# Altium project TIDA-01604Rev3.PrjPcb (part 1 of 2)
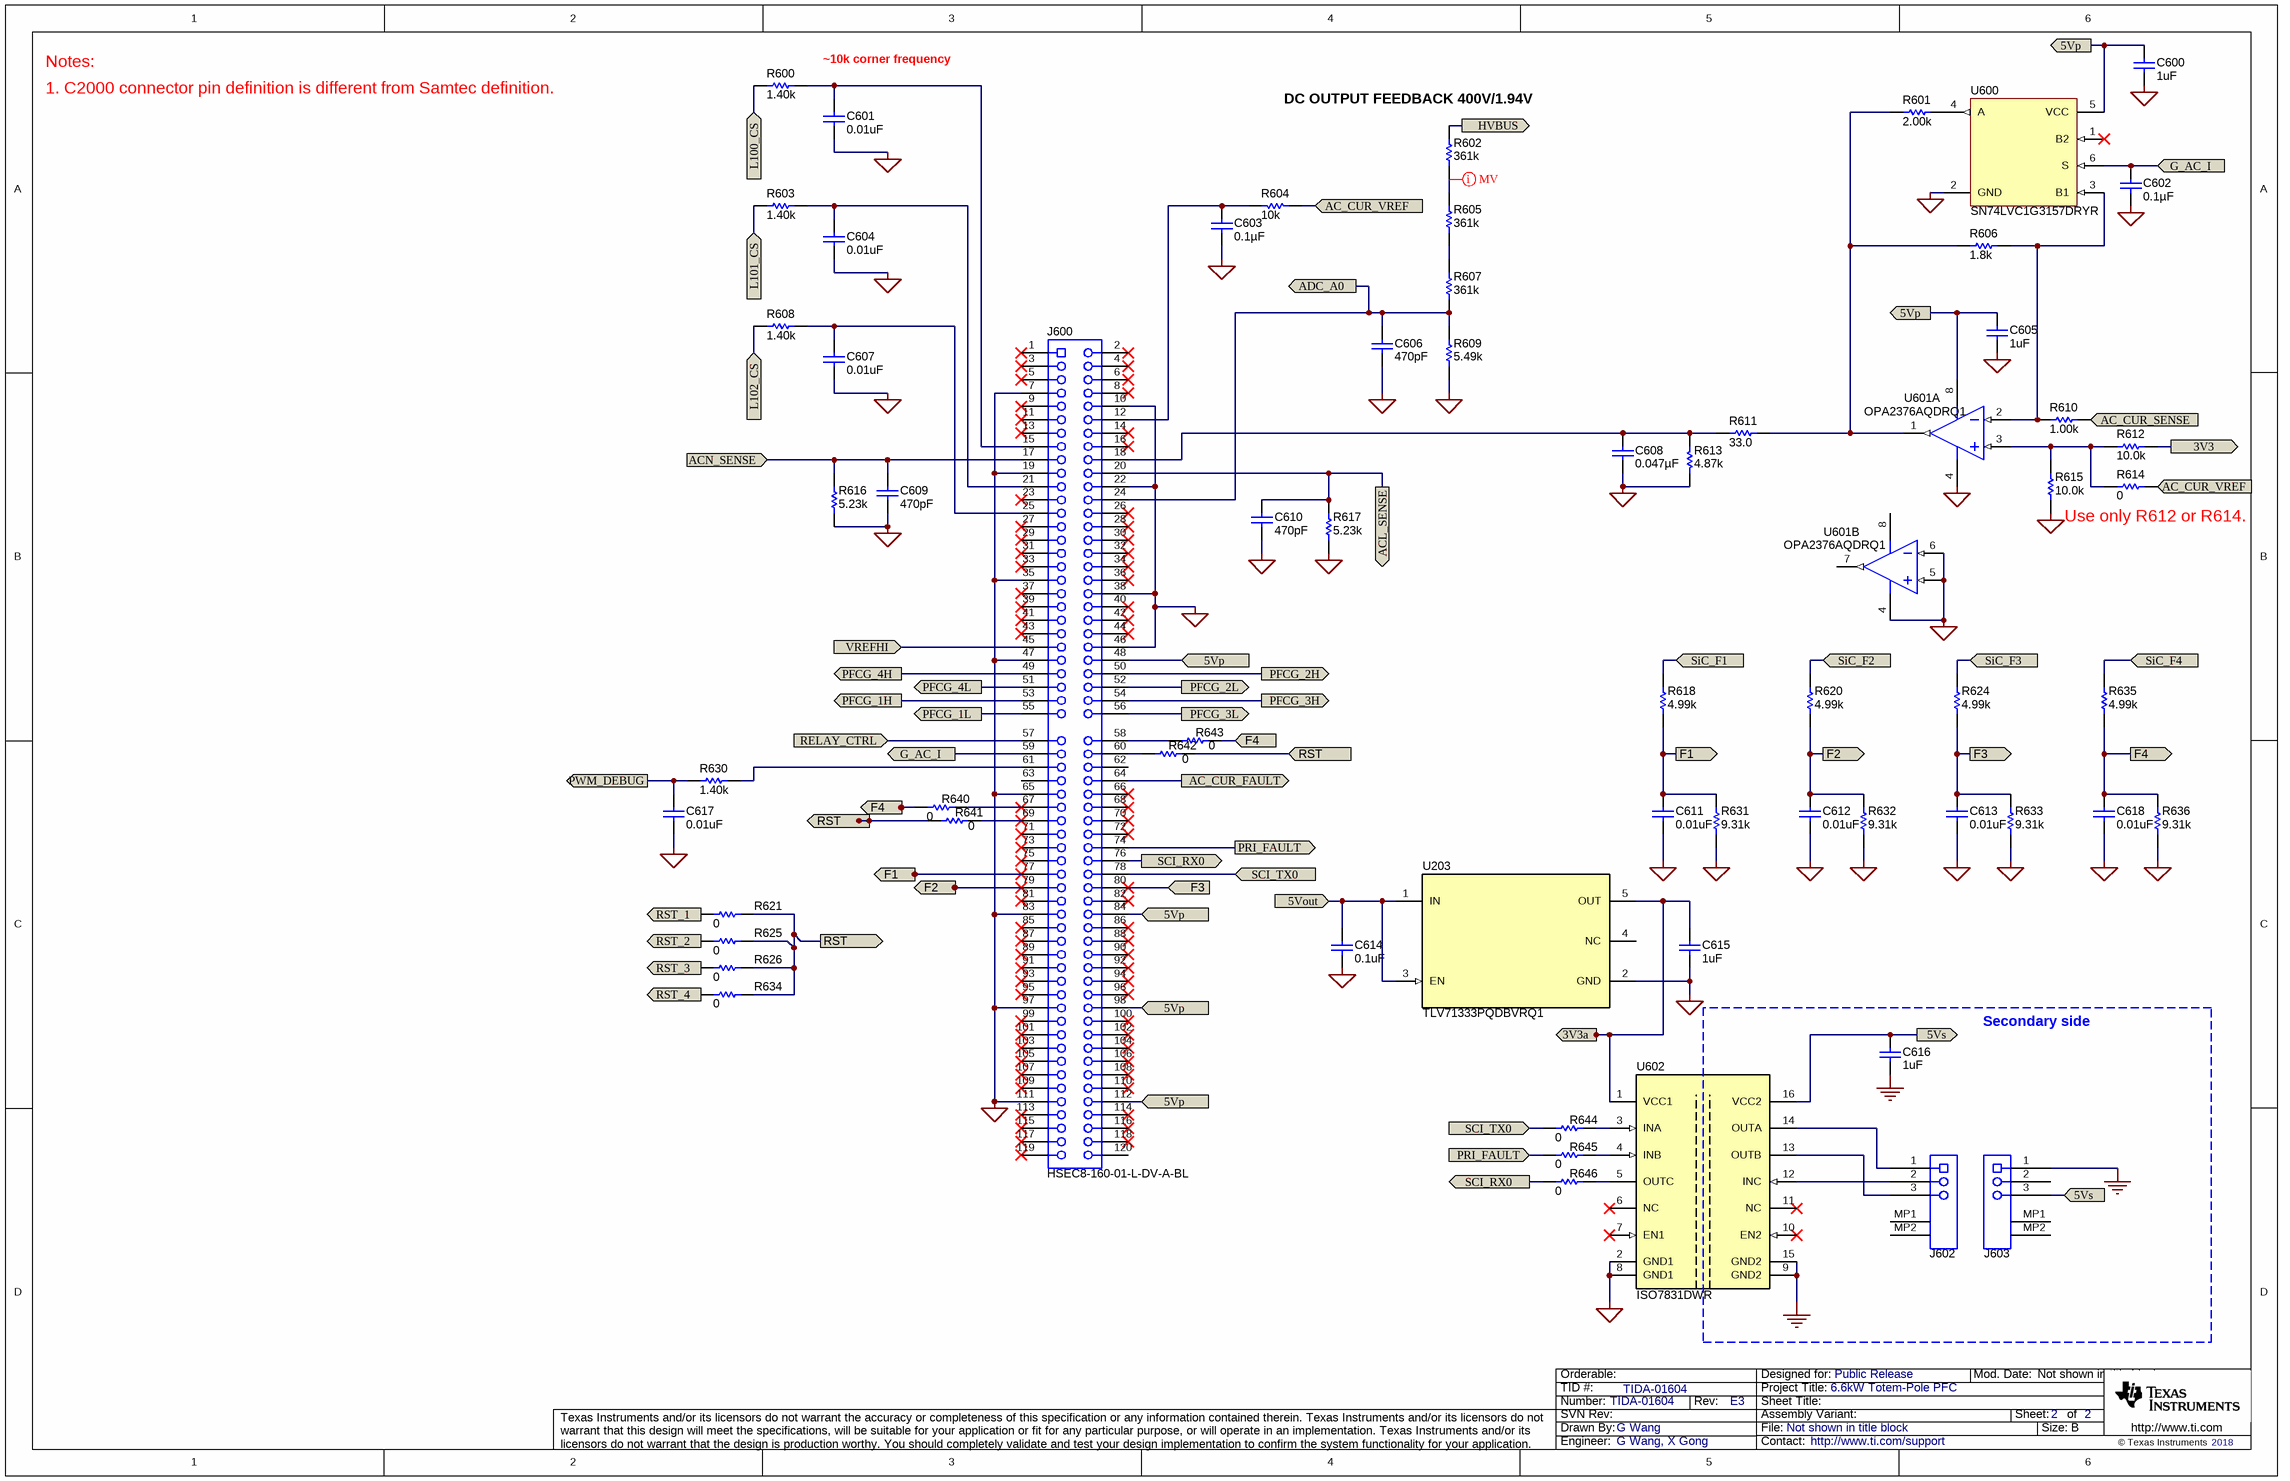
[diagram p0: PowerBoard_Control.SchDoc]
CopyrightYear: 2018; PCB_Layout: G Wang, X Gong; PCB_Rev: E3; PRJ_Customer: Public Release; PRJ_Engineer: G Wang, X Gong; PRJ_Number: TIDA-01604; PRJ_Title: 6.6kW Totem-Pole PFC; SCH_Rev: E3; TechSupport: http://www.ti.com/support; TID: TIDA-01604
3 sheets, 243 parts. Net scope: flat (ports and power ports of the same name join across sheets).
Board file: PowerBoard_PCB.PcbDoc
Sheets:
  PowerBoard_Control.SchDoc
  EVM_Hardware1.SchDoc
  PowerBoard.SchDoc

## Sheet PowerBoard_Control.SchDoc
size 431 x 279 mm; Date: Not shown in title block; ApprovedBy: Not shown in title block; CheckedBy: Not shown in title block; Author: Not shown in title block; CompanyName: Not shown in title block; DrawnBy: G Wang; Engineer: Not shown in title block; Organization: Not shown in title block; Address1: Not shown in title block; Address2: Not shown in title block; Address3: Not shown in title block; Address4: Not shown in title block; DocumentNumber: 2; Revision: Use project parameter SCH_Rev; SheetNumber: 2; SheetTotal: 2; PageSetup: Record=PageOptions¦CenterHorizontal=True¦CenterVertical=True¦PrintScale=1.00¦XCorrection=1.00¦YCorrection=1.00¦PrintKind=0¦BorderSize=5000000¦LeftOffset=0¦BottomOffset=0¦Orientation=2¦PaperLength=1000¦PaperWidth=1000¦Scale=100¦PaperSource=15¦PrintQuality=600¦MediaType=1¦DitherType=10¦PaperKind=Letter¦PrintScaleMode=1

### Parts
C600  ValueDisplayed: 1uF  [0603]  (hidden comment: C1608X7R1E105K080AB)
C601  ValueDisplayed: 0.01uF  [0402]  (hidden comment: GRM155R70J103KA01D)
C602  ValueDisplayed: 0.1µF  [0402]  (hidden comment: GCM155R71C104KA55D)
C603  ValueDisplayed: 0.1µF  [0402]  (hidden comment: GRM155R60J104KA01D)
C604  ValueDisplayed: 0.01uF  [0402]  (hidden comment: GRM155R70J103KA01D)
C605  ValueDisplayed: 1uF  [0603]  (hidden comment: C1608X7R1E105K080AB)
C606  ValueDisplayed: 470pF  [0402]  (hidden comment: GRM1555C1H471JA01D)
C607  ValueDisplayed: 0.01uF  [0402]  (hidden comment: GRM155R70J103KA01D)
C608  ValueDisplayed: 0.047µF  [0402]  (hidden comment: GRM155R60J472KA01D)
C609  ValueDisplayed: 470pF  [0402]  (hidden comment: GRM1555C1H471JA01D)
C610  ValueDisplayed: 470pF  [0402]  (hidden comment: GRM1555C1H471JA01D)
C611  ValueDisplayed: 0.01uF  [0402]  (hidden comment: GRM155R70J103KA01D)
C612  ValueDisplayed: 0.01uF  [0402]  (hidden comment: GRM155R70J103KA01D)
C613  ValueDisplayed: 0.01uF  [0402]  (hidden comment: GRM155R70J103KA01D)
C614  ValueDisplayed: 0.1uF  [0402]  (hidden comment: GRM155R70J104KA01D)
C615  ValueDisplayed: 1uF  [0603]  (hidden comment: C1608X7R1E105K080AB)
C616  ValueDisplayed: 1uF  [0603]  (hidden comment: C1608X7R1E105K080AB)
C617  ValueDisplayed: 0.01uF  [0402]  (hidden comment: GRM155R70J103KA01D)
C618  ValueDisplayed: 0.01uF  [0402]  (hidden comment: GRM155R70J103KA01D)
J600  HSEC8-160-01-L-DV-A-BL  [controlCARD-120HSEC]
J602  DF59-3S-2V(51)  [Hirose_DF59-3S-2V_51]  (value not drawn)
J603  DF59-3S-2V(51)  [Hirose_DF59-3S-2V_51]  (value not drawn)
R600  value 1.40k  [0402]  (hidden comment: CRCW04021K40FKED)
R601  ValueDisplayed: 2.00k  [0402]  (hidden comment: CRCW04022K00FKED)
R602  ValueDisplayed: 361k  [0805_HV]  (hidden comment: RT0805BRD07361KL)
R603  value 1.40k  [0402]  (hidden comment: CRCW04021K40FKED)
R604  value 10k  [0402]  (hidden comment: CRCW040210K0JNED)
R605  ValueDisplayed: 361k  [0805_HV]  (hidden comment: RT0805BRD07361KL)
R606  ValueDisplayed: 1.8k  [0402]  (hidden comment: CRCW04023K92FKED)
R607  ValueDisplayed: 361k  [0805_HV]  (hidden comment: RT0805BRD07361KL)
R608  value 1.40k  [0402]  (hidden comment: CRCW04021K40FKED)
R609  ValueDisplayed: 5.49k  [0805_HV]  (hidden comment: CRCW08055K49FKEA)
R610  ValueDisplayed: 1.00k  [0402]  (hidden comment: CRCW04021K00FKED)
R611  ValueDisplayed: 33.0  [0402]  (hidden comment: RC0402FR-0733RL)
R612  ValueDisplayed: 10.0k  [0402]  (hidden comment: CRCW040210K0FKED)  (no BOM)
R613  ValueDisplayed: 4.87k  [0402]  (hidden comment: ERA-2AEB4871X)
R614  ValueDisplayed: 0  [0402]  (hidden comment: CRCW04020000Z0ED)
R615  ValueDisplayed: 10.0k  [0402]  (hidden comment: CRCW040210K0FKED)
R616  ValueDisplayed: 5.23k  [0402]  (hidden comment: CRCW04025K23FKED)
R617  ValueDisplayed: 5.23k  [0402]  (hidden comment: CRCW04025K23FKED)
R618  ValueDisplayed: 4.99k  [0402]  (hidden comment: CRCW04024K99FKED)
R620  ValueDisplayed: 4.99k  [0402]  (hidden comment: CRCW04024K99FKED)
R621  ValueDisplayed: 0  [0402]  (hidden comment: CRCW04020000Z0ED)
R624  ValueDisplayed: 4.99k  [0402]  (hidden comment: CRCW04024K99FKED)
R625  ValueDisplayed: 0  [0402]  (hidden comment: CRCW04020000Z0ED)
R626  ValueDisplayed: 0  [0402]  (hidden comment: CRCW04020000Z0ED)
R630  value 1.40k  [0402]  (hidden comment: CRCW04021K40FKED)
R631  ValueDisplayed: 9.31k  [0402]  (hidden comment: CRCW04029K31FKED)
R632  ValueDisplayed: 9.31k  [0402]  (hidden comment: CRCW04029K31FKED)
R633  ValueDisplayed: 9.31k  [0402]  (hidden comment: CRCW04029K31FKED)
R634  ValueDisplayed: 0  [0402]  (hidden comment: CRCW04020000Z0ED)
R635  ValueDisplayed: 4.99k  [0402]  (hidden comment: CRCW04024K99FKED)
R636  ValueDisplayed: 9.31k  [0402]  (hidden comment: CRCW04029K31FKED)
R640  ValueDisplayed: 0  [0402]  (hidden comment: CRCW04020000Z0ED)
R641  ValueDisplayed: 0  [0402]  (hidden comment: CRCW04020000Z0ED)
R642  ValueDisplayed: 0  [0402]  (hidden comment: CRCW04020000Z0ED)
R643  ValueDisplayed: 0  [0402]  (hidden comment: CRCW04020000Z0ED)
R644  ValueDisplayed: 0  [0402]  (hidden comment: CRCW04020000Z0ED)
R645  ValueDisplayed: 0  [0402]  (hidden comment: CRCW04020000Z0ED)
R646  ValueDisplayed: 0  [0402]  (hidden comment: CRCW04020000Z0ED)
U203  TLV71333PQDBVRQ1  [DBV0005A_N]
U600  SN74LVC1G3157DRYR  [DRY0006A]
U601  OPA2376AQDRQ1  [D0008A_N]  (parts A,B of 2)
U602  ISO7831DWR  [DW0016B_N]

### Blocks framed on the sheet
Secondary side: C616 J602 J603 U602

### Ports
3V3 (out), 3V3a, 5Vout, 5Vp, 5Vs, AC_CUR_FAULT, AC_CUR_SENSE, AC_CUR_VREF, ACL_SENSE, ACN_SENSE, ADC_A0 (out), F1 (in), F1 (out), F2 (in), F2 (out), F3 (in), F3 (out), F4, F4 (out), G_AC_I (in), G_AC_I (out), HVBUS, L100_CS (in), L101_CS (in), L102_CS (in), PFCG_1H (out), PFCG_1L (out), PFCG_2H (out), PFCG_2L (out), PFCG_3H (out), PFCG_3L (out), PFCG_4H (out), PFCG_4L (out), PRI_FAULT (in), PRI_FAULT (out), PWM_DEBUG (out), RELAY_CTRL, RST, RST (out), RST_1 (out), RST_2 (out), RST_3 (out), RST_4 (out), SCI_RX0 (out), SCI_TX0, SCI_TX0 (in), SiC_F1 (in), SiC_F2 (in), SiC_F3 (in), SiC_F4 (in), VREFHI (in)

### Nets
PGND: C600.1 C601.2 C602.2 C603.1 C604.2 C605.1 C606.2 C607.2 C608.2 C609.2 C610.2 C611.2 C612.2 C613.2 C614.2 C615.1 C617.2 C618.2 J600.7 J600.10 J600.19 J600.22 J600.35 J600.38 J600.46 J600.47 J600.65 J600.83 J600.97 J600.111 R609.1 R613.1 R615.1 R616.1 R617.1 R631.1 R632.1 R633.1 R636.1 U203.2(GND) U600.2(GND) U601.4(V-) U601.5(IN_B+) U601.6(IN_B-) U602.2(GND1) U602.8(GND1)
SGND2: C616.1 J603.1 U602.9(GND2) U602.15(GND2)
3V3: R612.2 ; port 3V3
3V3a: C615.2 U203.5(OUT) U602.1(VCC1) ; port 3V3a
5Vout: C614.1 U203.1(IN) U203.3(EN) ; port 5Vout
5Vp: C600.2 C605.2 J600.48 J600.84 J600.98 J600.112 U600.5(VCC) U601.8(V+) ; port 5Vp
5Vs: C616.2 J603.3 U602.16(VCC2) ; port 5Vs
AC_CUR_FAULT: J600.64 ; port AC_CUR_FAULT
AC_CUR_SENSE: R610.1 ; port AC_CUR_SENSE
AC_CUR_VREF: R604.2 R614.2 ; port AC_CUR_VREF
ACL_SENSE: C610.1 J600.20 R617.2 ; port ACL_SENSE
ACN_SENSE: C609.1 J600.17 R616.2 ; port ACN_SENSE
ADC_A0: C606.1 J600.24 R607.2 R609.2 ; port ADC_A0
F1: C611.1 J600.77 R618.1 R631.2 ; port F1
F2: C612.1 J600.79 R620.1 R632.2 ; port F2
F3: C613.1 J600.80 R624.1 R633.2 ; port F3
F4: C618.1 R635.1 R636.2 R640.1 R643.2 ; port F4
G_AC_I: C602.1 J600.59 U600.6(S) ; port G_AC_I
HVBUS: R602.2 ; port HVBUS
L100_CS: R600.1 ; port L100_CS
L101_CS: R603.1 ; port L101_CS
L102_CS: R608.1 ; port L102_CS
PFCG_1H: J600.53 ; port PFCG_1H
PFCG_1L: J600.55 ; port PFCG_1L
PFCG_2H: J600.50 ; port PFCG_2H
PFCG_2L: J600.52 ; port PFCG_2L
PFCG_3H: J600.54 ; port PFCG_3H
PFCG_3L: J600.56 ; port PFCG_3L
PFCG_4H: J600.49 ; port PFCG_4H
PFCG_4L: J600.51 ; port PFCG_4L
PRI_FAULT: J600.74 R645.1 ; port PRI_FAULT
PWM_DEBUG: C617.1 R630.1 ; port PWM_DEBUG
RELAY_CTRL: J600.57 ; port RELAY_CTRL
RST: R621.2 R625.2 R626.2 R634.2 R641.1 R642.2 ; port RST
RST_1: R621.1 ; port RST_1
RST_2: R625.1 ; port RST_2
RST_3: R626.1 ; port RST_3
RST_4: R634.1 ; port RST_4
SCI_RX0: J600.76 R646.1 ; port SCI_RX0
SCI_TX0: J600.78 R644.1 ; port SCI_TX0
SiC_F1: R618.2 ; port SiC_F1
SiC_F2: R620.2 ; port SiC_F2
SiC_F3: R624.2 ; port SiC_F3
SiC_F4: R635.2 ; port SiC_F4
VREFHI: J600.45 ; port VREFHI
NetC601_1: C601.1 J600.15 R600.2
NetC603_2: C603.2 J600.12 R604.1
NetC604_1: C604.1 J600.21 R603.2
NetC607_1: C607.1 J600.25 R608.2
NetC608_1: C608.1 J600.18 R611.1 R613.2
NetJ600_58: J600.58 R643.1
NetJ600_60: J600.60 R642.1
NetJ600_61: J600.61 R630.2
NetJ600_67: J600.67 R640.2
NetJ600_69: J600.69 R641.2
NetJ602_1: J602.1 U602.14(OUTA)
NetJ602_2: J602.2 U602.12(INC)
NetJ602_3: J602.3 U602.13(OUTB)
NetR601_1: R601.1 R606.1 R611.2 U601.1(OUT_A)
NetR601_2: R601.2 U600.4(A)
NetR602_1: R602.1 R605.1
NetR605_2: R605.2 R607.1
NetR606_2: R606.2 R610.2 U600.3(B1) U601.2(IN_A-)
NetR612_1: R612.1 R614.1 R615.2 U601.3(IN_A+)
NetR644_2: R644.2 U602.3(INA)
NetR645_2: R645.2 U602.4(INB)
NetR646_2: R646.2 U602.5(OUTC)

Not connected (* = marked no-connect by the designer): J600 1* 2* 3* 4* 5* 6* 8* 9* 11* 13* 14* 16* 23* 26* 27* 28* 29* 30* 31* 32* 33* 34* 36* 37* 39* 40* 41* 42* 43* 44* 62 63 66* 68* 70* 71* 72* 73* 75* 81* 82* 85* 86* 87* 88* 89* 90* 91* 92* 93* 94* 95* 96* 99* 100* 101* 102* 103* 104* 105* 106* 107* 108* 109* 110* 113* 114* 115* 116* 117* 118* 119* 120; J602 MP1 MP2; J603 2 MP1 MP2; U203 4(NC); U600 1(B2)*; U601 7(OUT_B); U602 6(NC)* 7(EN1)* 10(EN2)* 11(NC)*

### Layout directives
net class MV: NetR602_1

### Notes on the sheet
- Notes:
- 1. C2000 connector pin definition is different from Samtec definition.
- 0k corner frequency
- (near R602) DC OUTPUT FEEDBACK 400V/1.94V
- Use only R612 or R614.

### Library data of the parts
C600 C605 C615 C616 = C1608X7R1E105K080AB: CAP, CERM, 1uF, 25V, +/-10%, X7R, 0603; Manufacturer: TDK; Polarized: N; CompType: Capacitor; U/M: EA; Cap_F: 0.000001; Tolerance_%: 10; Value1: Unknown; VDC_V: 25; TaMin_C: -55; TaMax_C: 125
C601 C604 C607 C611-C613 C617 C618 = GRM155R70J103KA01D: CAP, CERM, 0.01uF, 6.3V, +/-10%, X7R, 0402; Manufacturer: MuRata; Polarized: N; CompType: Capacitor; U/M: EA; Cap_F: 0.00000001; Tolerance_%: 10; Value1: Unknown; VDC_V: 6.3; TaMin_C: -55; TaMax_C: 125
C602 = GCM155R71C104KA55D: CAP, CERM, 0.1 µF, 16 V, +/- 10%, X7R, 0402; Manufacturer: MuRata; Polarized: N; CompType: Capacitor; Value: 0.1uF; U/M: EA; Cap_F: 0.0000001; Tolerance_%: 10; Value1: Unknown; VDC_V: 16; Value2: 16V; TaMin_C: -55; TaMax_C: 125; SizeArea_mm2: 0.5; SizeAreaWB_mm2: 3; SizeX_mm: 1; SizeZ_mm: 0.6; AEC Category: Q200
C603 = GRM155R60J104KA01D: CAP, CERM, 0.1uF, 6.3V, +/-10%, X5R, 0402; Manufacturer: MuRata; Polarized: N; CompType: Capacitor; U/M: EA; Cap_F: 0.0000001; Tolerance_%: 10; Value1: Unknown; VDC_V: 6.3; TaMin_C: -55; TaMax_C: 85
C606 C609 C610 = GRM1555C1H471JA01D: CAP, CERM, 470 pF, 50 V,+/- 5%, C0G/NP0, 0402; Manufacturer: MuRata; Polarized: N; CompType: Capacitor; Value: 470pF; U/M: EA; Cap_F: 0.00000000047; Tolerance_%: 5; VDC_V: 50; Value2: 50V; TaMin_C: -55; TaMax_C: 125; SizeArea_mm2: 0.5; SizeAreaWB_mm2: 3; SizeX_mm: 1; SizeZ_mm: 0.6; AEC Category: Q200; Green_Lifecycle: Active; Green_REACh: Passed
C608 = C1005X5R1A473K050BA: CAP, CERM, 0.047 µF, 10 V, +/- 10%, X5R, 0402; Manufacturer: TDK; Polarized: N; CompType: Capacitor; Value: 0.047uF; U/M: EA; Cap_F: 0.000000047; Tolerance_%: 10; Value1: Unknown; Value2: 10V; TaMin_C: -55; TaMax_C: 85; SizeArea_mm2: 0.5; SizeAreaWB_mm2: 3; SizeX_mm: 1; SizeZ_mm: 0.6; AEC Category: Q200
C614 = GRM155R70J104KA01D: CAP, CERM, 0.1uF, 6.3V, +/-10%, X7R, 0402; Manufacturer: MuRata; Polarized: N; CompType: Capacitor; U/M: EA; Cap_F: 0.0000001; Tolerance_%: 10; Value1: Unknown; VDC_V: 6.3; TaMin_C: -55; TaMax_C: 125
J600 = controlCARD-120HSEC: C2000 controlCARD-120HSEC connector, SMT; Manufacturer: Samtec; SymbolCreator: a0412235; Note: The pin numbering does not match Samtec datasheet
J602 J603 = DF59-3S-2V(51): Receptacle, 2mm, 3x1, Gold, Natural, SMT; Manufacturer: Hirose Electric Co. Ltd.; SymbolCreator: Altium; Pitch_mm: 2; Gender: Female; Row_Count: 1; Current_A: 3; Voltage_V: 230; Cert_UL: Y
R600 R603 R608 R630 = CRCW04021K40FKED: RES, 1.40k ohm, 1%, 0.063W, 0402; Manufacturer: Vishay-Dale; CompType: Resistor; Res_ohm: 1400; Value_Code: 1k40; Tolerance_%: 1; Power_W: 0.063; VDC_V: 50; TempCo: 100 ppm/C; EIA_Code: E96; U/M: EA
R601 = CRCW04022K00FKED: RES, 2.00 k, 1%, 0.063 W, 0402; Manufacturer: Vishay-Dale; CompType: Resistor; Value: 2.00k; Res_ohm: 2000; Value_Code: 2k00; Tolerance_%: 1; Power_W: 0.063; Value2: 0.063W; VDC_V: 50; TempCo: 100 ppm/C; SizeArea_mm2: 0.5; SizeZ_mm: 0.6; EIA_Code: E96; U/M: EA; AEC Category: Q200
R602 R605 R607 = RT0805BRD07361KL: RES, 361 k, 0.1%, 0.125 W, 0805; Manufacturer: Yageo America; CompType: Resistor; Value: 361k; Res_ohm: 361000; Tolerance_%: 0.1; Power_W: 0.125; Value2: 0.125W; VDC_V: 150; TempCo: 25 ppm/C; SizeArea_mm2: 2.5; SizeX_mm: 2; SizeY_mm: 1.25; SizeZ_mm: 1.45; EIA_Code: E192; U/M: EA; AEC Category: Q200
R604 = CRCW040210K0JNED: RES, 10k ohm, 5%, 0.063W, 0402; Manufacturer: Vishay-Dale; CompType: Resistor; Res_ohm: 10000; Value_Code: 10k0; Tolerance_%: 5; Power_W: 0.063; VDC_V: 50; TempCo: 200 ppm/C; EIA_Code: E24; U/M: EA
R606 = CRCW04021K80JNED: RES, 1.8 k, 5%, 0.063 W, 0402; Manufacturer: Vishay-Dale; CompType: Resistor; Value: 1.8k; Res_ohm: 1800; Value_Code: 1k80; Tolerance_%: 5; Power_W: 0.063; Value2: 0.063W; VDC_V: 50; TempCo: 200 ppm/C; SizeArea_mm2: 0.5; SizeX_mm: 1; SizeZ_mm: 0.6; EIA_Code: E24; U/M: EA; AEC Category: Q200
R609 = CRCW08055K49FKEA: RES, 5.49 k, 1%, 0.125 W, 0805; Manufacturer: Vishay-Dale; CompType: Resistor; Value: 5.49k; Res_ohm: 5490; Value_Code: 5k49; Tolerance_%: 1; Power_W: 0.125; Value2: 0.125W; VDC_V: 150; TempCo: 100 ppm/C; SizeArea_mm2: 2.5; SizeX_mm: 2; SizeY_mm: 1.25; SizeZ_mm: 1.45; EIA_Code: E96; U/M: EA; AEC Category: Q200
R610 = CRCW04021K00FKED: RES, 1.00 k, 1%, 0.063 W, 0402; Manufacturer: Vishay-Dale; CompType: Resistor; Value: 1.00k; Res_ohm: 1000; Value_Code: 1k00; Tolerance_%: 1; Power_W: 0.063; Value2: 0.063W; VDC_V: 50; TempCo: 100 ppm/C; SizeArea_mm2: 0.5; SizeZ_mm: 0.6; EIA_Code: E96; U/M: EA; AEC Category: Q200
R611 = RC0402FR-0733RL: RES, 33.0, 1%, 0.062 W, 0402; Manufacturer: Yageo America; CompType: Resistor; Value: 33.0; Res_ohm: 33; Value_Code: 33R0; Tolerance_%: 1; Power_W: 0.062; Value2: 0.062W; VDC_V: 50; TempCo: 100 ppm/C; SizeArea_mm2: 0.5; SizeZ_mm: 0.6; U/M: EA; AEC Category: Q200; AEC Qualified: N; Green_Lifecycle: Active; Green_REACh: Passed
R612 R615 = CRCW040210K0FKED: RES, 10.0 k, 1%, 0.063 W, 0402; Manufacturer: Vishay-Dale; CompType: Resistor; Value: 10.0k; Res_ohm: 10000; Value_Code: 10k0; Tolerance_%: 1; Power_W: 0.063; Value2: 0.063W; VDC_V: 50; TempCo: 100 ppm/C; SizeArea_mm2: 0.5; SizeZ_mm: 0.6; EIA_Code: E96; U/M: EA; AEC Category: Q200
R613 = ERA-2AEB4871X: RES, 4.87 k, 0.1%, 0.062 W, AEC-Q200 Grade 0, 0402; Manufacturer: Panasonic; CompType: Resistor; Value: 4.87k; Res_ohm: 4870; Value_Code: 4k87; Tolerance_%: 0.1; Power_W: 0.062; Value2: 0.062W; VDC_V: 25; TempCo: 25 ppm/C; EIA_Code: E192; U/M: EA; AEC Category: Q200; AEC Qualified: Y; AEC Grade: 0
R614 R621 R625 R626 R634 R640-R646 = CRCW04020000Z0ED: RES, 0, 5%, 0.063 W, 0402; Manufacturer: Vishay-Dale; CompType: Resistor; Value: 0; Value_Code: 0000; Tolerance_%: 5; Power_W: 0.063; Value2: 0.063W; VDC_V: 50; TempCo: 200 ppm/C; SizeArea_mm2: 0.5; SizeX_mm: 1; SizeZ_mm: 0.6; EIA_Code: E24; U/M: EA; AEC Category: Q200
R616 R617 = CRCW04025K23FKED: RES, 5.23 k, 1%, 0.063 W, 0402; Manufacturer: Vishay-Dale; CompType: Resistor; Value: 5.23k; Res_ohm: 5230; Value_Code: 5k23; Tolerance_%: 1; Power_W: 0.063; Value2: 0.063W; VDC_V: 50; TempCo: 100 ppm/C; SizeArea_mm2: 0.5; SizeZ_mm: 0.6; EIA_Code: E96; U/M: EA; AEC Category: Q200; Green_Lifecycle: Active; Green_REACh: Passed
R618 R620 R624 R635 = CRCW04024K99FKED: RES, 4.99 k, 1%, 0.063 W, 0402; Manufacturer: Vishay-Dale; CompType: Resistor; Value: 4.99k; Res_ohm: 4990; Value_Code: 4k99; Tolerance_%: 1; Power_W: 0.063; Value2: 0.063W; VDC_V: 50; TempCo: 100 ppm/C; SizeArea_mm2: 0.5; SizeZ_mm: 0.6; EIA_Code: E96; U/M: EA; AEC Category: Q200
R631-R633 R636 = CRCW04029K31FKED: RES, 9.31 k, 1%, 0.063 W, 0402; Manufacturer: Vishay-Dale; CompType: Resistor; Value: 9.31k; Res_ohm: 9310; Value_Code: 9k31; Tolerance_%: 1; Power_W: 0.063; Value2: 0.063W; VDC_V: 50; TempCo: 100 ppm/C; SizeArea_mm2: 0.5; SizeZ_mm: 0.6; EIA_Code: E96; U/M: EA; AEC Category: Q200
U203 = TLV71333PQDBVRQ1: Capacitor-Free, 150-mA, Low-Dropout Regulator with Foldback Current Limit for Portable Devices, DBV0005A; Manufacturer: Texas Instruments; SymbolCreator: Altium; SizeArea_mm2: 8.12; SizeAreaWB_mm2: 14.82; SizeX_mm: 2.8; SizeY_mm: 2.9; SizeZ_mm: 1.45; CompType: IC; U/M: EA
U600 = SN74LVC1G3157DRYR: SINGLE-POLE DOUBLE-THROW ANALOG SWITCH, DRY0006A; Manufacturer: Texas Instruments; SymbolCreator: a0799628; CompType: IC; U/M: EA
U601 = OPA2376AIDG4: Precision, Low Noise, Low Quiescent Current Operational Amplifier, 2 to 5.5 V, -40 to 125 degC, 8-pin SOIC (D0008A), Green (RoHS & no Sb/Br); Manufacturer: Texas Instruments; Alternate PartNumber: Equivalent; CMRR(Min)(dB): 76; IIB(Max)(pA): 10; Iq per channel(Max)(mA): 0.95; Number of Channels: 2; Offset Drift(Typ)(uV/C): 0.32; Sub Family: Low Input Bias Current Amp (<=10pA), Low Noise Amp (<=10nV/rtHz), Low Offset Voltage Amplifier (<=500uV), Low Supply Voltage Amplifier (<=2.7V), Precision Amplifier; Total Supply Voltage(Max)(+5V is 5, +/-5V is 10): 5.5; Vio (25C)(Max)(mV): 0.025; Vn at 1kHz(Typ)(nV/rtHz): 7.5
U602 = ISO7831DWR: High-Performance, 8000 VPK Reinforced Triple Digital Isolator, DW0016B; Manufacturer: Texas Instruments; SymbolCreator: Altium; SizeArea_mm2: 107.12; SizeAreaWB_mm2: 152.52; SizeX_mm: 10.4; SizeY_mm: 10.3; SizeZ_mm: 2.65; CompType: IC; U/M: EA

## Sheet EVM_Hardware1.SchDoc
size 431 x 279 mm; Date: Not shown in title block; ApprovedBy: Not shown in title block; CheckedBy: Not shown in title block; Author: Not shown in title block; CompanyName: Not shown in title block; DrawnBy: G Wang; Engineer: Not shown in title block; Organization: Not shown in title block; Address1: Not shown in title block; Address2: Not shown in title block; Address3: Not shown in title block; Address4: Not shown in title block; DocumentNumber: 1; Revision: Use project parameter SCH_Rev; SheetNumber: 3; SheetTotal: 3; PageSetup: Record=PageOptions¦CenterHorizontal=True¦CenterVertical=True¦PrintScale=1.00¦XCorrection=1.00¦YCorrection=1.00¦PrintKind=0¦BorderSize=5000000¦LeftOffset=0¦BottomOffset=0¦Orientation=2¦PaperLength=1000¦PaperWidth=1000¦Scale=100¦PaperSource=15¦PrintQuality=600¦MediaType=1¦DitherType=10¦PaperKind=Letter¦PrintScaleMode=1
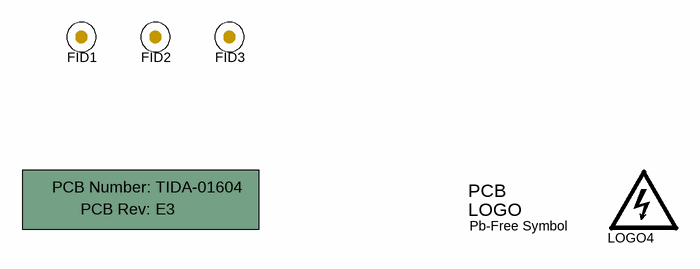
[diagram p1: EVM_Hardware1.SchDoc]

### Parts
!PCB  Printed Circuit Board  (value not drawn)  (mechanical)
FID1  Fiducial  [Fiducial10-20]  (value not drawn)
FID2  Fiducial  [Fiducial10-20]  (value not drawn)
FID3  Fiducial  [Fiducial10-20]  (value not drawn)
Logo3  Pb-Free Symbol  [Pb-Free_Overlay_Small]  (no BOM)
LOGO4  DANGER HIGH VOLTAGE  [IEC_HighVoltage_Small]  (value not drawn)  (no BOM)

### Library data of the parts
!PCB = PCB: Manufacturer: Any; PartNumber: TIDA-01604; SymbolCreator: a0412235
FID1-FID3 = Fiducial: Fiducial mark.  There is nothing to buy or mount.; SymbolCreator: codlsc
Logo3 = Pb-Free: SymbolCreator: a0412235
LOGO4 = IEC_HighVoltage: IEC 61010-1 High Voltage Warning; SymbolCreator: a0412235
